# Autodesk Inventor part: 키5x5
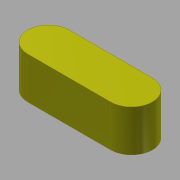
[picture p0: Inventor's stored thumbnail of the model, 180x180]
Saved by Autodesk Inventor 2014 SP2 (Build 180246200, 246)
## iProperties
Created: 2011-04
Part Number: 키5x5
Document SubType Name: Modeling
Designer: pww
Density: 7.86 g/cm^3
Material: 강철, 연강
Appearance: 노란색
Author: pww
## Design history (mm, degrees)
sketch "스케치1"
  geometry: L1 (-5, -2.5)-(5, -2.5); L2 (5, 2.5)-(-5, 2.5); A1 r 2.5 centre (-5, 0) between (-5, 2.5) and (-5, -2.5); A2 r 2.5 centre (5, 0) between (5, -2.5) and (5, 2.5); 1 further point
  constraints: 4 end point, 4 point on circle, 2 centre point
extrude "돌출1" new body sketch "스케치1" distance "d0" = 5; taper "d1" = 0 deg
node "솔리드1"
